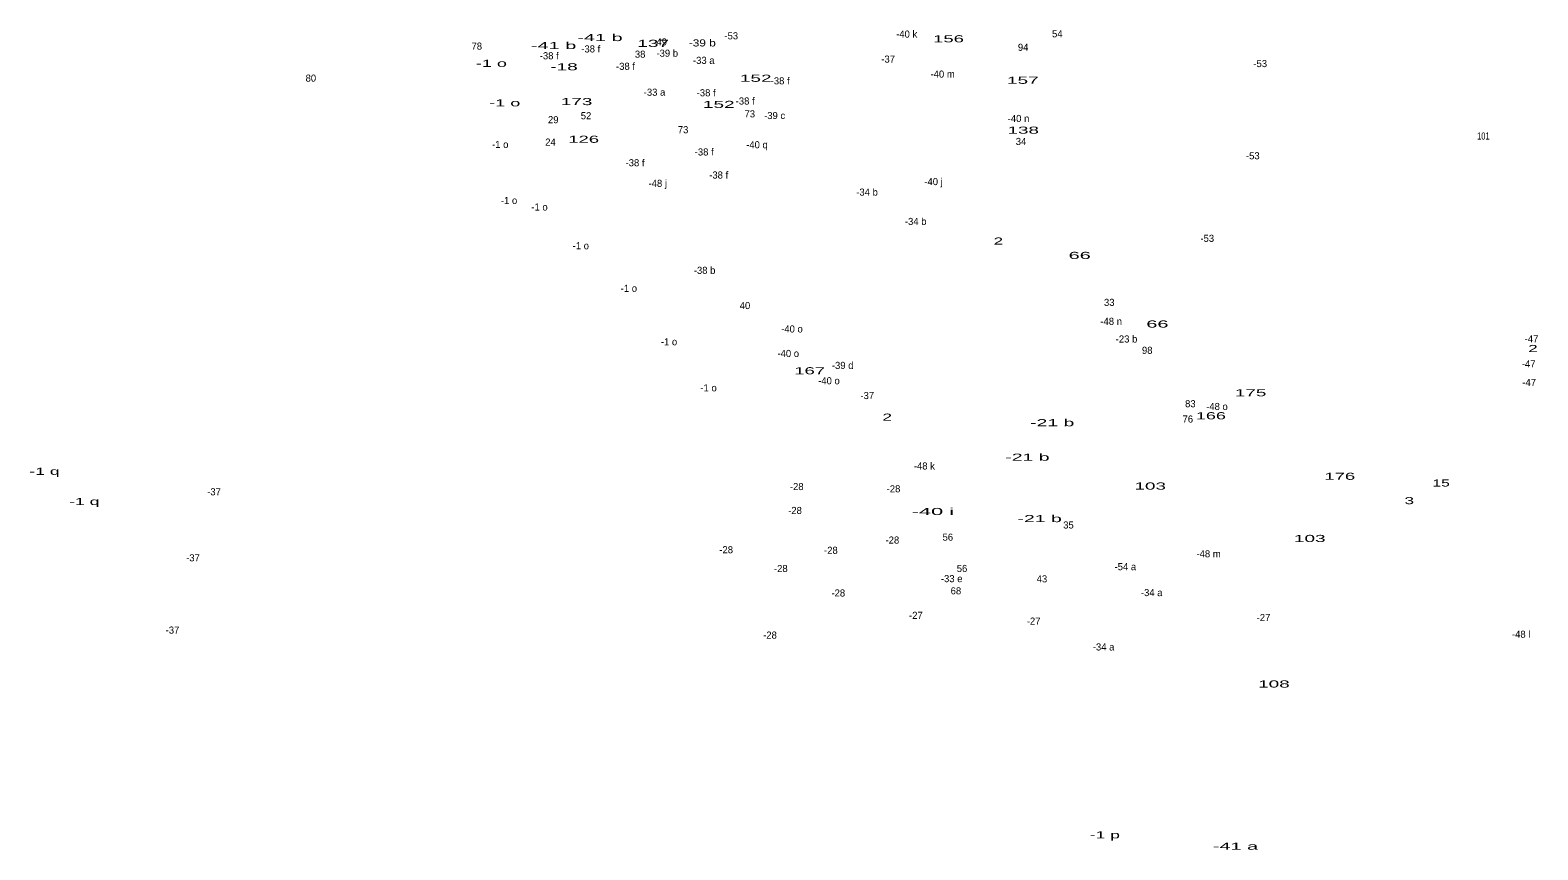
# Model space of a CAD drawing. Extents: x -668622 to -666786, y -990362 to -986505.
# Drawn here: x -667797 to -666946, y -989381 to -988918 of the extents above; entities that cross this region are included whole.
import ezdxf
from ezdxf.enums import TextEntityAlignment as Align

# ---------------------------------------------------------------- set-up
doc = ezdxf.new("R2010")
doc.units = 0
doc.header["$LTSCALE"] = 1.6
doc.layers.add('24', color=7, linetype='Continuous')

msp = doc.modelspace()

# ---------------------------------------------------------------- texts
at = {"layer": '24'}
for s, width, p in [('-41 b', 2.1, (-667475.587, -988924.46)), ('137', 2, (-667445.553, -988927.74)), ('-39 b', 1.25, (-667417.821, -988927.5)), ('156', 1.95, (-667278.823, -988925.15)), ('-41 b', 2.1, (-667501.767, -988928.96)), ('-1 o', 1.9, (-667536.857, -988939)), ('-18', 2, (-667495.871, -988940.95)), ('152', 2, (-667387.667, -988947.44)), ('157', 2, (-667236.893, -988948.58)), ('-1 o', 1.9, (-667529.307, -988961.33)), ('173', 2, (-667488.803, -988960.62)), ('152', 2, (-667408.507, -988962.2)), ('138', 2, (-667236.667, -988976.74)), ('126', 1.95, (-667484.793, -988981.89)), ('101', 0.8, (-666976.94, -988980.06)), ('2', 1.8, (-667250.691, -989039.37)), ('66', 2.1, (-667204.761, -989047.48)), ('66', 2.1, (-667160.911, -989086.22)), ('2', 1.8, (-666948.931, -989100.03)), ('167', 1.95, (-667357.217, -989112.61)), ('175', 2, (-667108.313, -989125.03)), ('2', 1.8, (-667313.441, -989138.8)), ('166', 1.9, (-667130.727, -989138.02)), ('-21 b', 2.05, (-667220.311, -989141.95)), ('-21 b', 2.05, (-667234.291, -989161.4)), ('-1 q', 1.85, (-667789.151, -989169.39)), ('176', 1.95, (-667057.967, -989172.21)), ('103', 2, (-667164.974, -989177.71)), ('15', 1.65, (-667000.757, -989175.99)), ('-1 q', 1.85, (-667766.661, -989186.42)), ('-40 i', 2.3, (-667287.667, -989192.08)), ('3', 1.8, (-667018.731, -989185.96)), ('-21 b', 2.05, (-667227.381, -989196.1)), ('103', 2, (-667074.914, -989207.3)), ('108', 2, (-667095.144, -989289.49)), ('-1 p', 1.85, (-667190.601, -989374.68)), ('-41 a', 2.1, (-667116.867, -989381.1))]:
    msp.add_text(s, height=4, dxfattribs=dict(at, width=width)).set_placement(p, align=Align.CENTER)
for s, p in [('49', (-667440.717, -988926.9)), ('-53', (-667401.475, -988923.47)), ('-40 k', (-667302.444, -988922.49)), ('54', (-667217.421, -988922.34)), ('78', (-667545.103, -988929.29)), ('-38 f', (-667504.225, -988934.74)), ('-38 f', (-667480.775, -988930.88)), ('38', (-667452.907, -988933.83)), ('-39 b', (-667437.614, -988933.29)), ('-37', (-667312.921, -988936.62)), ('94', (-667236.697, -988929.94)), ('-38 f', (-667461.175, -988940.69)), ('-33 a', (-667416.993, -988937.33)), ('-40 m', (-667282.151, -988945.08)), ('-53', (-667102.895, -988939.16)), ('80', (-667638.791, -988947.36)), ('-38 f', (-667373.865, -988948.9)), ('-33 a', (-667444.783, -988955.32)), ('-38 f', (-667415.635, -988955.64)), ('-38 f', (-667393.625, -988960.3)), ('29', (-667501.953, -988970.83)), ('52', (-667483.457, -988968.59)), ('73', (-667391.013, -988967.55)), ('-39 c', (-667376.984, -988968.5)), ('-40 n', (-667239.32, -988970.15)), ('73', (-667428.683, -988976.49)), ('-1 o', (-667531.87, -988984.79)), ('24', (-667503.521, -988983.48)), ('-40 q', (-667386.955, -988984.99)), ('34', (-667237.911, -988983.11)), ('-38 f', (-667455.785, -988995.17)), ('-38 f', (-667416.755, -988989.06)), ('-53', (-667107.075, -988991.22)), ('-38 f', (-667408.565, -989002.08)), ('-48 j', (-667442.96, -989006.79)), ('-34 b', (-667324.832, -989011.74)), ('-40 j', (-667287.288, -989005.8)), ('-1 o', (-667526.89, -989016.44)), ('-1 o', (-667509.7, -989020.13)), ('-34 b', (-667297.362, -989028.29)), ('-53', (-667132.775, -989037.82)), ('-1 o', (-667486.41, -989041.99)), ('-38 b', (-667416.523, -989055.91)), ('-1 o', (-667459.26, -989066.06)), ('40', (-667393.725, -989075.81)), ('33', (-667188.097, -989074)), ('-40 o', (-667367.2, -989089.01)), ('-48 n', (-667187.022, -989084.7)), ('-1 o', (-667436.61, -989096.23)), ('-23 b', (-667178.353, -989094.67)), ('-47', (-666949.765, -989094.61)), ('-40 o', (-667369.29, -989102.83)), ('98', (-667166.673, -989101.06)), ('-39 d', (-667338.584, -989109.58)), ('-47', (-666951.375, -989108.75)), ('-1 o', (-667414.29, -989122.24)), ('-40 o', (-667346.32, -989118.25)), ('-47', (-666951.045, -989119.2)), ('-37', (-667324.701, -989126.61)), ('83', (-667142.337, -989131.23)), ('-48 o', (-667127.302, -989132.78)), ('76', (-667143.748, -989139.87)), ('-48 k', (-667292.476, -989166.38)), ('-37', (-667693.441, -989180.96)), ('-28', (-667364.515, -989178)), ('-28', (-667309.895, -989179.28)), ('-28', (-667365.475, -989191.5)), ('35', (-667211.127, -989199.7)), ('-28', (-667310.535, -989208.21)), ('56', (-667279.223, -989206.58)), ('-28', (-667404.345, -989213.67)), ('-28', (-667345.235, -989213.99)), ('-48 m', (-667132.033, -989216)), ('-37', (-667705.321, -989218.24)), ('-28', (-667373.505, -989224.27)), ('56', (-667271.213, -989224.24)), ('-54 a', (-667179.012, -989223.23)), ('-33 e', (-667277.053, -989230)), ('43', (-667226.111, -989230.13)), ('-28', (-667341.055, -989238.09)), ('68', (-667274.663, -989236.9)), ('-34 a', (-667164.152, -989237.88)), ('-27', (-667297.261, -989250.73)), ('-27', (-667101.041, -989251.95)), ('-37', (-667716.891, -989259.05)), ('-27', (-667230.781, -989253.98)), ('-28', (-667379.615, -989261.87)), ('-34 a', (-667191.302, -989268.57)), ('-48 l', (-666955.585, -989261.4))]:
    msp.add_text(s, height=4, dxfattribs=at).set_placement(p, align=Align.CENTER)

doc.saveas('drawing.dxf')
